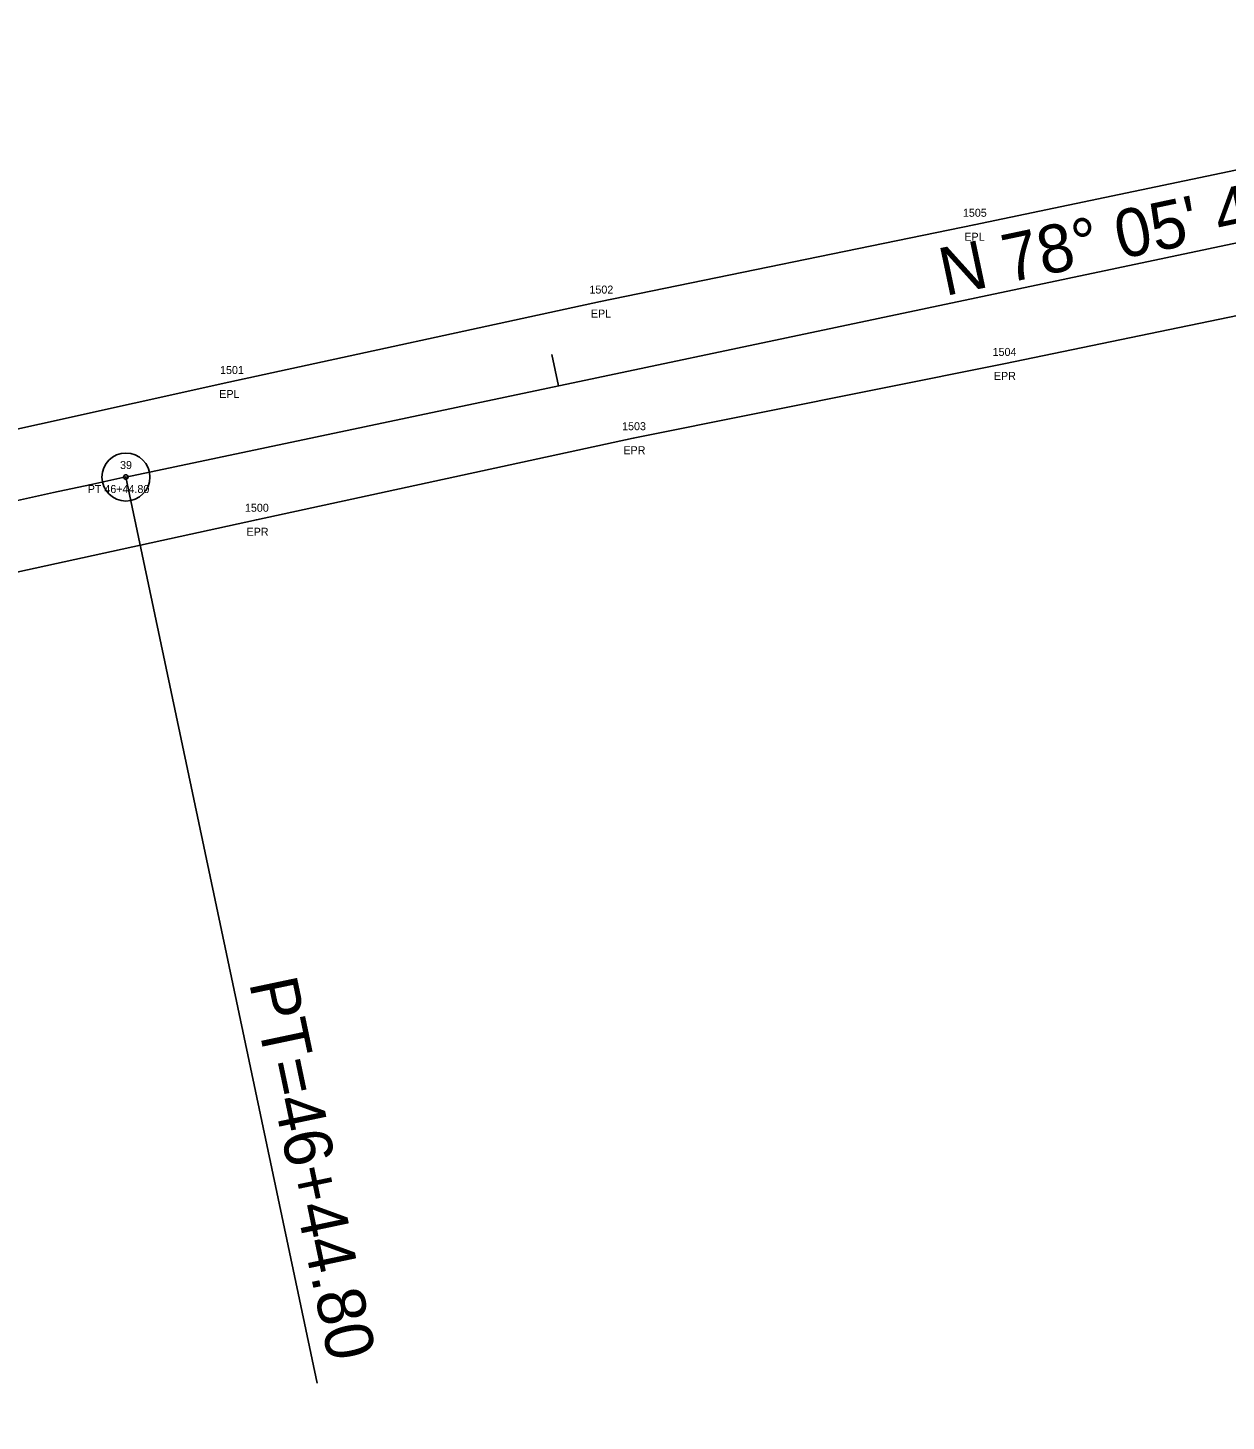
# Model space of a CAD drawing. Extents: x 1965304 to 1970247, y 1117014 to 1118201.
# Drawn here: x 1966413 to 1966562.7, y 1117249.2 to 1117423.3 of the extents above; entities that cross this region are included whole.
import ezdxf

# ---------------------------------------------------------------- set-up
doc = ezdxf.new("R2010")
doc.units = 0
for name, color, linetype in [('RD_EX_Road', 7, 'Continuous'), ('RD_EX_Road_txCode', 7, 'Continuous'), ('RD_HC_Cl', 7, 'Continuous'), ('RD_HC_Data', 7, 'Continuous'), ('RD_HC_Data_Tic', 7, 'Continuous'), ('RD_HC_txCode', 7, 'Continuous'), ('RD_SMD_Locator', 7, 'Continuous')]:
    doc.layers.add(name, color=color, linetype=linetype)

msp = doc.modelspace()

# ---------------------------------------------------------------- linework, layer by layer
at = {"layer": 'RD_EX_Road'}
for points in [[(1966031.82, 1117232.96), (1966074.66, 1117252.15), (1966117.78, 1117271.58), (1966161.06, 1117290.48), (1966205.41, 1117309.23), (1966251.25, 1117327.39), (1966297.25, 1117343.1), (1966344.08, 1117357.04), (1966390.78, 1117368.56), (1966438.12, 1117379.08), (1966484.55, 1117389.13), (1966531.2, 1117398.73), (1966578.39, 1117408.59), (1966604.53, 1117414.06), (1966624.54, 1117418.32), (1966671.32, 1117428.35), (1966716.51, 1117439.32), (1966736.6, 1117445.59), (1966754.13, 1117451.44), (1966759.66, 1117453.52), (1966769.51, 1117457.48)], [(1965729.99, 1117080.3), (1965819.77, 1117119.13), (1965907.74, 1117159.31), (1965995.36, 1117199.04), (1966039.27, 1117218.5), (1966081.24, 1117237.15), (1966124.67, 1117256.55), (1966167.66, 1117275.55), (1966211.47, 1117293.63), (1966257.79, 1117311.58), (1966302.7, 1117327.21), (1966347.9, 1117339.98), (1966394.81, 1117351.64), (1966441.56, 1117361.87), (1966488.62, 1117372.06), (1966534.91, 1117381.34), (1966581.23, 1117390.95), (1966629.53, 1117400.95), (1966675.63, 1117411.11), (1966721.68, 1117422.85), (1966766.8, 1117438.97), (1966775.75, 1117440.57)]]:
    msp.add_lwpolyline(points, dxfattribs=at)
at = {"layer": 'RD_HC_Cl'}
msp.add_line((1966425.26, 1117367.21), (1966684.87, 1117421.95), dxfattribs=at)
msp.add_arc((1966705.48, 1116038.04), 1358.39, 101.90472, 114.38256, dxfattribs=at)
at = {"layer": 'RD_HC_Data'}
msp.add_line((1966425.26, 1117367.21), (1966449.13, 1117253.99), dxfattribs=at)
for radius in [3, 3, 0.282, 0.282]:
    msp.add_circle((1966425.26, 1117367.21), radius, dxfattribs=at)
at = {"layer": 'RD_HC_Data_Tic'}
msp.add_line((1966479.28, 1117378.6), (1966478.45, 1117382.52), dxfattribs=at)
at = {"layer": 'RD_SMD_Locator'}
for centre in [(1966531.2, 1117398.73), (1966531.2, 1117398.73), (1966484.55, 1117389.13), (1966484.55, 1117389.13), (1966534.91, 1117381.34), (1966534.91, 1117381.34), (1966438.12, 1117379.08), (1966438.12, 1117379.08), (1966488.62, 1117372.06), (1966488.62, 1117372.06), (1966425.26, 1117367.21), (1966425.26, 1117367.21), (1966441.56, 1117361.87), (1966441.56, 1117361.87)]:
    msp.add_circle(centre, 0.001, dxfattribs=at)

# ---------------------------------------------------------------- texts
at = {"layer": 'RD_EX_Road_txCode'}
for s, p in [('1505', (1966529.81, 1117399.73)), ('1505', (1966529.81, 1117399.73)), ('EPL', (1966529.99, 1117396.73)), ('EPL', (1966529.99, 1117396.73)), ('1502', (1966483.16, 1117390.13)), ('1502', (1966483.16, 1117390.13)), ('EPL', (1966483.34, 1117387.13)), ('EPL', (1966483.34, 1117387.13)), ('1504', (1966533.52, 1117382.34)), ('1504', (1966533.52, 1117382.34)), ('1501', (1966437.02, 1117380.08)), ('1501', (1966437.02, 1117380.08)), ('EPR', (1966533.68, 1117379.34)), ('EPR', (1966533.68, 1117379.34)), ('EPL', (1966436.92, 1117377.08)), ('EPL', (1966436.92, 1117377.08)), ('1503', (1966487.24, 1117373.06)), ('1503', (1966487.24, 1117373.06)), ('EPR', (1966487.4, 1117370.06)), ('EPR', (1966487.4, 1117370.06)), ('1500', (1966440.13, 1117362.87)), ('1500', (1966440.13, 1117362.87)), ('EPR', (1966440.33, 1117359.87)), ('EPR', (1966440.33, 1117359.87))]:
    msp.add_text(s, height=1, dxfattribs=at).set_placement(p)
at = {"layer": 'RD_HC_Data'}
for s, rotation, p in [('N 78%%d 05\' 43" E', 11.9047, (1966527.58, 1117389.81)), ('PT=46+44.80', 281.9047, (1966440.63, 1117304.03))]:
    msp.add_text(s, height=6, rotation=rotation, dxfattribs=at).set_placement(p)
at = {"layer": 'RD_HC_txCode'}
for s, p in [('39', (1966424.53, 1117368.21)), ('39', (1966424.53, 1117368.21)), ('PT 46+44.80', (1966420.49, 1117365.21)), ('PT 46+44.80', (1966420.49, 1117365.21))]:
    msp.add_text(s, height=1, dxfattribs=at).set_placement(p)

doc.saveas('drawing.dxf')
